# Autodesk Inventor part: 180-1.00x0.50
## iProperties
Created: 2007-06
Part Number: 180-1.00x0.50
Document SubType Name: Modeling
Designer: btaylor
Density: 1 g/cm^3
Author: btaylor
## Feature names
1. Extrusion1
2. Extrusion2
3. Extrusion3
4. Fillet1
5. Extrusion4
6. Extrusion5
7. Extrusion6
8. Fillet14
9. Fillet15
10. Fillet17
11. Fillet18
12. Fillet19
13. Fillet20
14. Fillet21
15. Fillet22
16. Fillet23
17. Chamfer1
18. Chamfer2
